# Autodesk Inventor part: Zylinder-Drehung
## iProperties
Created: 2010-05
Part Number: Zylinder-Drehung
Material: Standard
Document SubType Name: Blech
Designer: Udo.Huebner
Density: 1 g/cm^3
Sheet Metal Rule: Standard_mm
Flat Pattern Width: 90 cm
Flat Pattern Length: 217.398 cm
Flat Pattern Area: 19565.8 cm^2
Author: Udo.Huebner
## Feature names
1. Umdrehung1 [Revolution]
2. Rechteckige Anordnung1 [Rectangular Pattern]
3. Ausklinkung1
